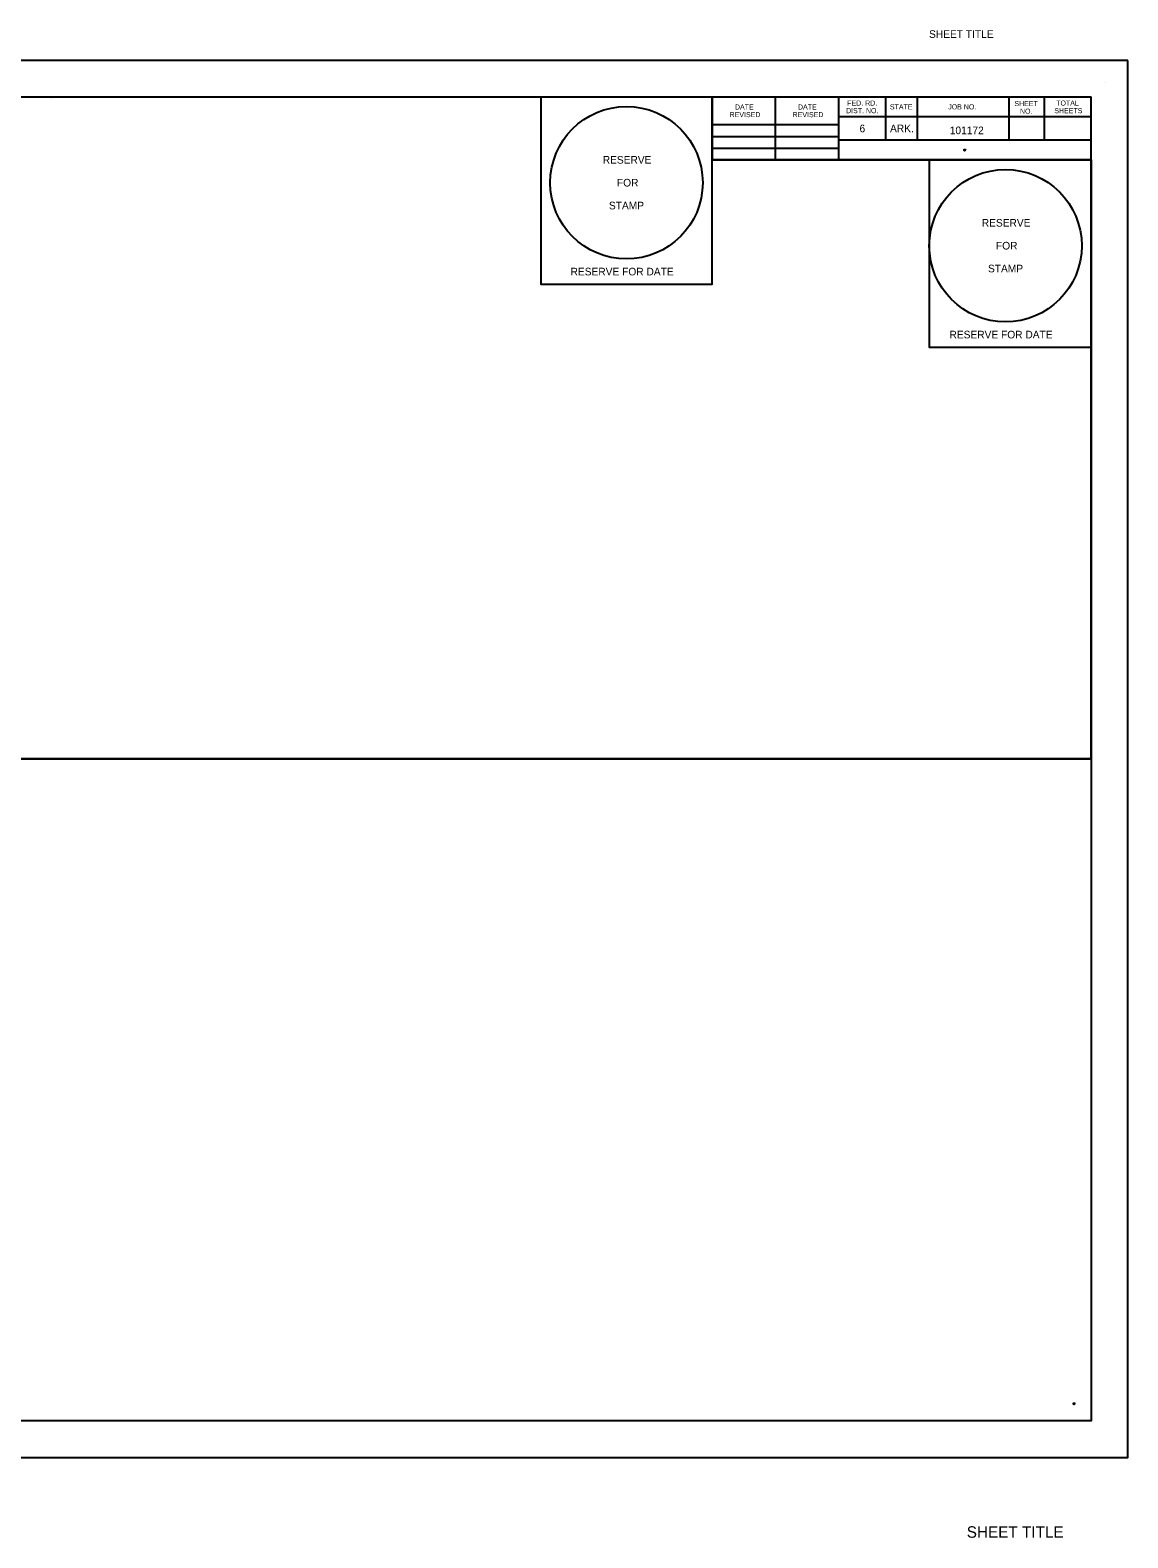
# Model space of a CAD drawing. Extents: x 0 to 17, y -0.6 to 11.2.
# Drawn here: x 8.36 to 17, y -0.63 to 11.24 of the extents above; entities that cross this region are included whole.
import ezdxf

# ---------------------------------------------------------------- set-up
doc = ezdxf.new("R2010")
doc.units = 0
for name, color, linetype in [('G-ANNO-TEXT', 7, 'Continuous'), ('G-Border-Paper', 7, 'Continuous'), ('G-Border-Sheet', 7, 'Continuous'), ('G-No Plot-Anchor', 7, 'Continuous'), ('G-No Plot-Border-1', 7, 'Continuous'), ('G-No Plot-Border-2', 7, 'Continuous'), ('G-No Plot-Stamp-1', 7, 'Continuous'), ('G-No Plot-Stamp-2', 7, 'Continuous'), ('G-Table-Major', 7, 'Continuous'), ('G-Table-Minor', 7, 'Continuous')]:
    doc.layers.add(name, color=color, linetype=linetype)

msp = doc.modelspace()

# ---------------------------------------------------------------- linework, layer by layer
at = {"layer": 'G-ANNO-TEXT'}
msp.add_line((16.821, 10.827), (16.821, 10.827), dxfattribs=at)
at = {"layer": 'G-Border-Paper'}
msp.add_lwpolyline([(17, 11), (0, 11), (0, 0), (17, 0)], close=True, dxfattribs=at)
at = {"layer": 'G-Border-Sheet'}
for p in [(0.758, 10.712), (16.712, 5.5)]:
    msp.add_line(p, (16.712, 10.712), dxfattribs=at)
msp.add_lwpolyline([(0.758, 5.5), (16.712, 5.5), (16.712, 0.288), (0.758, 0.288)], close=True, dxfattribs=at)
at = {"layer": 'G-No Plot-Anchor'}
for centre in [(15.716, 10.294), (16.577, 0.423)]:
    msp.add_circle(centre, 0.005, dxfattribs=at)
at = {"layer": 'G-No Plot-Border-1'}
msp.add_lwpolyline([(0.758, 5.5), (0.758, 10.712), (13.728, 10.712), (13.728, 10.216), (14.721, 10.216), (14.802, 10.216), (15.437, 10.216), (15.437, 8.741), (16.712, 8.741), (16.712, 5.5)], close=True, dxfattribs=at)
at = {"layer": 'G-No Plot-Border-2'}
msp.add_lwpolyline([(0.758, 5.5), (0.758, 10.712), (12.378, 10.712), (12.378, 9.237), (13.728, 9.237), (13.728, 10.216), (14.721, 10.216), (14.926, 10.216), (16.712, 10.216), (16.712, 5.5)], close=True, dxfattribs=at)
at = {"layer": 'G-No Plot-Stamp-1'}
msp.add_circle((16.037, 9.541), 0.6, dxfattribs=at)
at = {"layer": 'G-No Plot-Stamp-2'}
msp.add_circle((13.053, 10.037), 0.6, dxfattribs=at)
at = {"layer": 'G-Table-Major'}
for p, q in [((13.728, 10.217), (13.728, 10.712)), ((14.721, 10.712), (14.721, 10.216)), ((13.728, 10.495), (14.721, 10.495)), ((16.712, 10.216), (13.728, 10.216))]:
    msp.add_line(p, q, dxfattribs=at)
at = {"layer": 'G-Table-Minor'}
for p, q in [((8.529, 10.699), (8.529, 10.699)), ((8.529, 10.699), (8.529, 10.699)), ((14.226, 10.216), (14.226, 10.712)), ((15.093, 10.712), (15.093, 10.372)), ((15.341, 10.712), (15.341, 10.372)), ((16.062, 10.712), (16.062, 10.372)), ((16.34, 10.712), (16.34, 10.372)), ((16.712, 10.566), (16.712, 10.566)), ((16.712, 10.556), (14.721, 10.556)), ((13.728, 10.401), (14.721, 10.401)), ((16.712, 10.372), (14.721, 10.372)), ((13.728, 10.31), (14.721, 10.31))]:
    msp.add_line(p, q, dxfattribs=at)

# ---------------------------------------------------------------- texts
at = {"layer": 'G-ANNO-TEXT'}
for s, height, p in [('SHEET TITLE', 0.06, (15.435, 11.177)), ('TOTAL', 0.04, (16.436, 10.644)), ('REVISED', 0.04, (13.865, 10.553)), ('DATE', 0.04, (13.907, 10.613)), ('REVISED', 0.04, (14.361, 10.553)), ('DATE', 0.04, (14.403, 10.613)), ('DIST. NO.', 0.04, (14.782, 10.584)), ('FED. RD.', 0.04, (14.791, 10.644)), ('STATE', 0.04, (15.127, 10.614)), ('JOB NO.', 0.04, (15.586, 10.614)), ('SHEET', 0.04, (16.107, 10.64)), ('NO.', 0.04, (16.151, 10.58)), ('SHEETS', 0.04, (16.421, 10.584)), ('6', 0.06, (14.888, 10.434)), ('ARK.', 0.06, (15.128, 10.434)), ('101172', 0.06, (15.598, 10.419)), ('SHEET TITLE', 0.09, (15.732, -0.632))]:
    msp.add_text(s, height=height, dxfattribs=at).set_placement(p)
at = {"layer": 'G-No Plot-Stamp-1'}
for s, p in [('RESERVE', (15.85, 9.691)), ('FOR ', (15.962, 9.511)), ('STAMP', (15.899, 9.331)), ('RESERVE FOR DATE', (15.596, 8.811))]:
    msp.add_text(s, height=0.06, dxfattribs=at).set_placement(p)
at = {"layer": 'G-No Plot-Stamp-2'}
for s, p in [('RESERVE', (12.866, 10.187)), ('FOR ', (12.978, 10.007)), ('STAMP', (12.915, 9.827)), ('RESERVE FOR DATE', (12.613, 9.307))]:
    msp.add_text(s, height=0.06, dxfattribs=at).set_placement(p)

doc.saveas('drawing.dxf')
